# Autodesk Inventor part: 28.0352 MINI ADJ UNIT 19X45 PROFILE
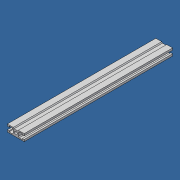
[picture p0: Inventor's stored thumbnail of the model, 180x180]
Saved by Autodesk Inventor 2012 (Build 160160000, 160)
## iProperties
Created: 2015-11
Part Number: 28.0352 MINI ADJ UNIT 19X45 PROFILE
Material: Aluminum-6061
Description: PROFILE 19X45
Document SubType Name: Modeling
Designer: Admin
Stock Number: 20.1001 PROFILE 19X45
Density: 2.71 g/cm^3
Company: MiniTec Framing Systems, LLC
Author: Admin
FINISH: CLEAR ANODIZED
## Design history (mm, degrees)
sketch "Sketch1"
  geometry: L1 (22.5, -9.5)-(-22.5, -9.5) reference; L2 (22.5, -4.1)-(18, -4.1) reference; L3 (18, -6.8)-(9.5, -6.8) reference; L4 (9.5, -6.8)-(7.2, -4.5) reference; L5 (7.2, -4.5)-(7.2, 4.5) reference; L6 (7.2, 4.5)-(9.5, 6.8) reference; L7 (9.5, 6.8)-(18, 6.8) reference; L8 (18, 6.8)-(18, 4.6) reference; L9 (18, 4.1)-(22.5, 4.1) reference; L10 (7.214, 9.5)-(22.5, 9.5) reference; L11 (4.5, 7.2)-(6.8, 9.5) reference; L12 (-4.5, 7.2)-(4.5, 7.2) reference; L13 (-6.8, 9.5)-(-4.5, 7.2) reference; L14 (-22.5, 4.1)-(-18, 4.1) reference; L15 (-18, 4.6)-(-18, 6.8) reference; L16 (-18, 6.8)-(-9.5, 6.8) reference; L17 (-9.5, 6.8)-(-7.2, 4.5) reference; L18 (-7.2, 4.5)-(-7.2, -4.5) reference; L19 (-7.2, -4.5)-(-9.5, -6.8) reference; L20 (-9.5, -6.8)-(-18, -6.8) reference; L21 (-18, -4.1)-(-22.5, -4.1) reference; L22 (-22.5, 9.5)-(-6.8, 9.5) reference; L23 (6.8, 9.5)-(7.214, 9.5) reference; L24 (18, 4.6)-(18, 4.1) reference; L25 (18, -4.1)-(18, -6.8) reference; L26 (22.5, 9.5)-(22.5, 4.1) reference; L27 (-22.5, -9.5)-(-22.5, -4.1) reference; L28 (-18, -6.8)-(-18, -4.1) reference; L29 (-18, 4.1)-(-18, 4.6) reference; L30 (-22.5, 9.5)-(-22.5, 4.1); L31 (22.5, -9.5)-(22.5, -4.1); C1 r 3.75 at (0, 0) reference
  constraints: 62 end point, 13 horizontal, 10 vertical, 3 parallel, 1 centre point, 39 other
extrude "Extrusion2" new body sketch "Sketch1" stored distance "d57" = 399.8; taper "d58" = 0 deg
body "Solid2"
